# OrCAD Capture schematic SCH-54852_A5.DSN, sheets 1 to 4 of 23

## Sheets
1 C-07 CPU MISC: size C; title: MCIMX93-QSB; rev: A5; company: NXP Semiconductor; note: SCH-54852  PDF: SPF-54852; note: NO. 192 Liangjing Rd. Pudong New Area, ShangHai
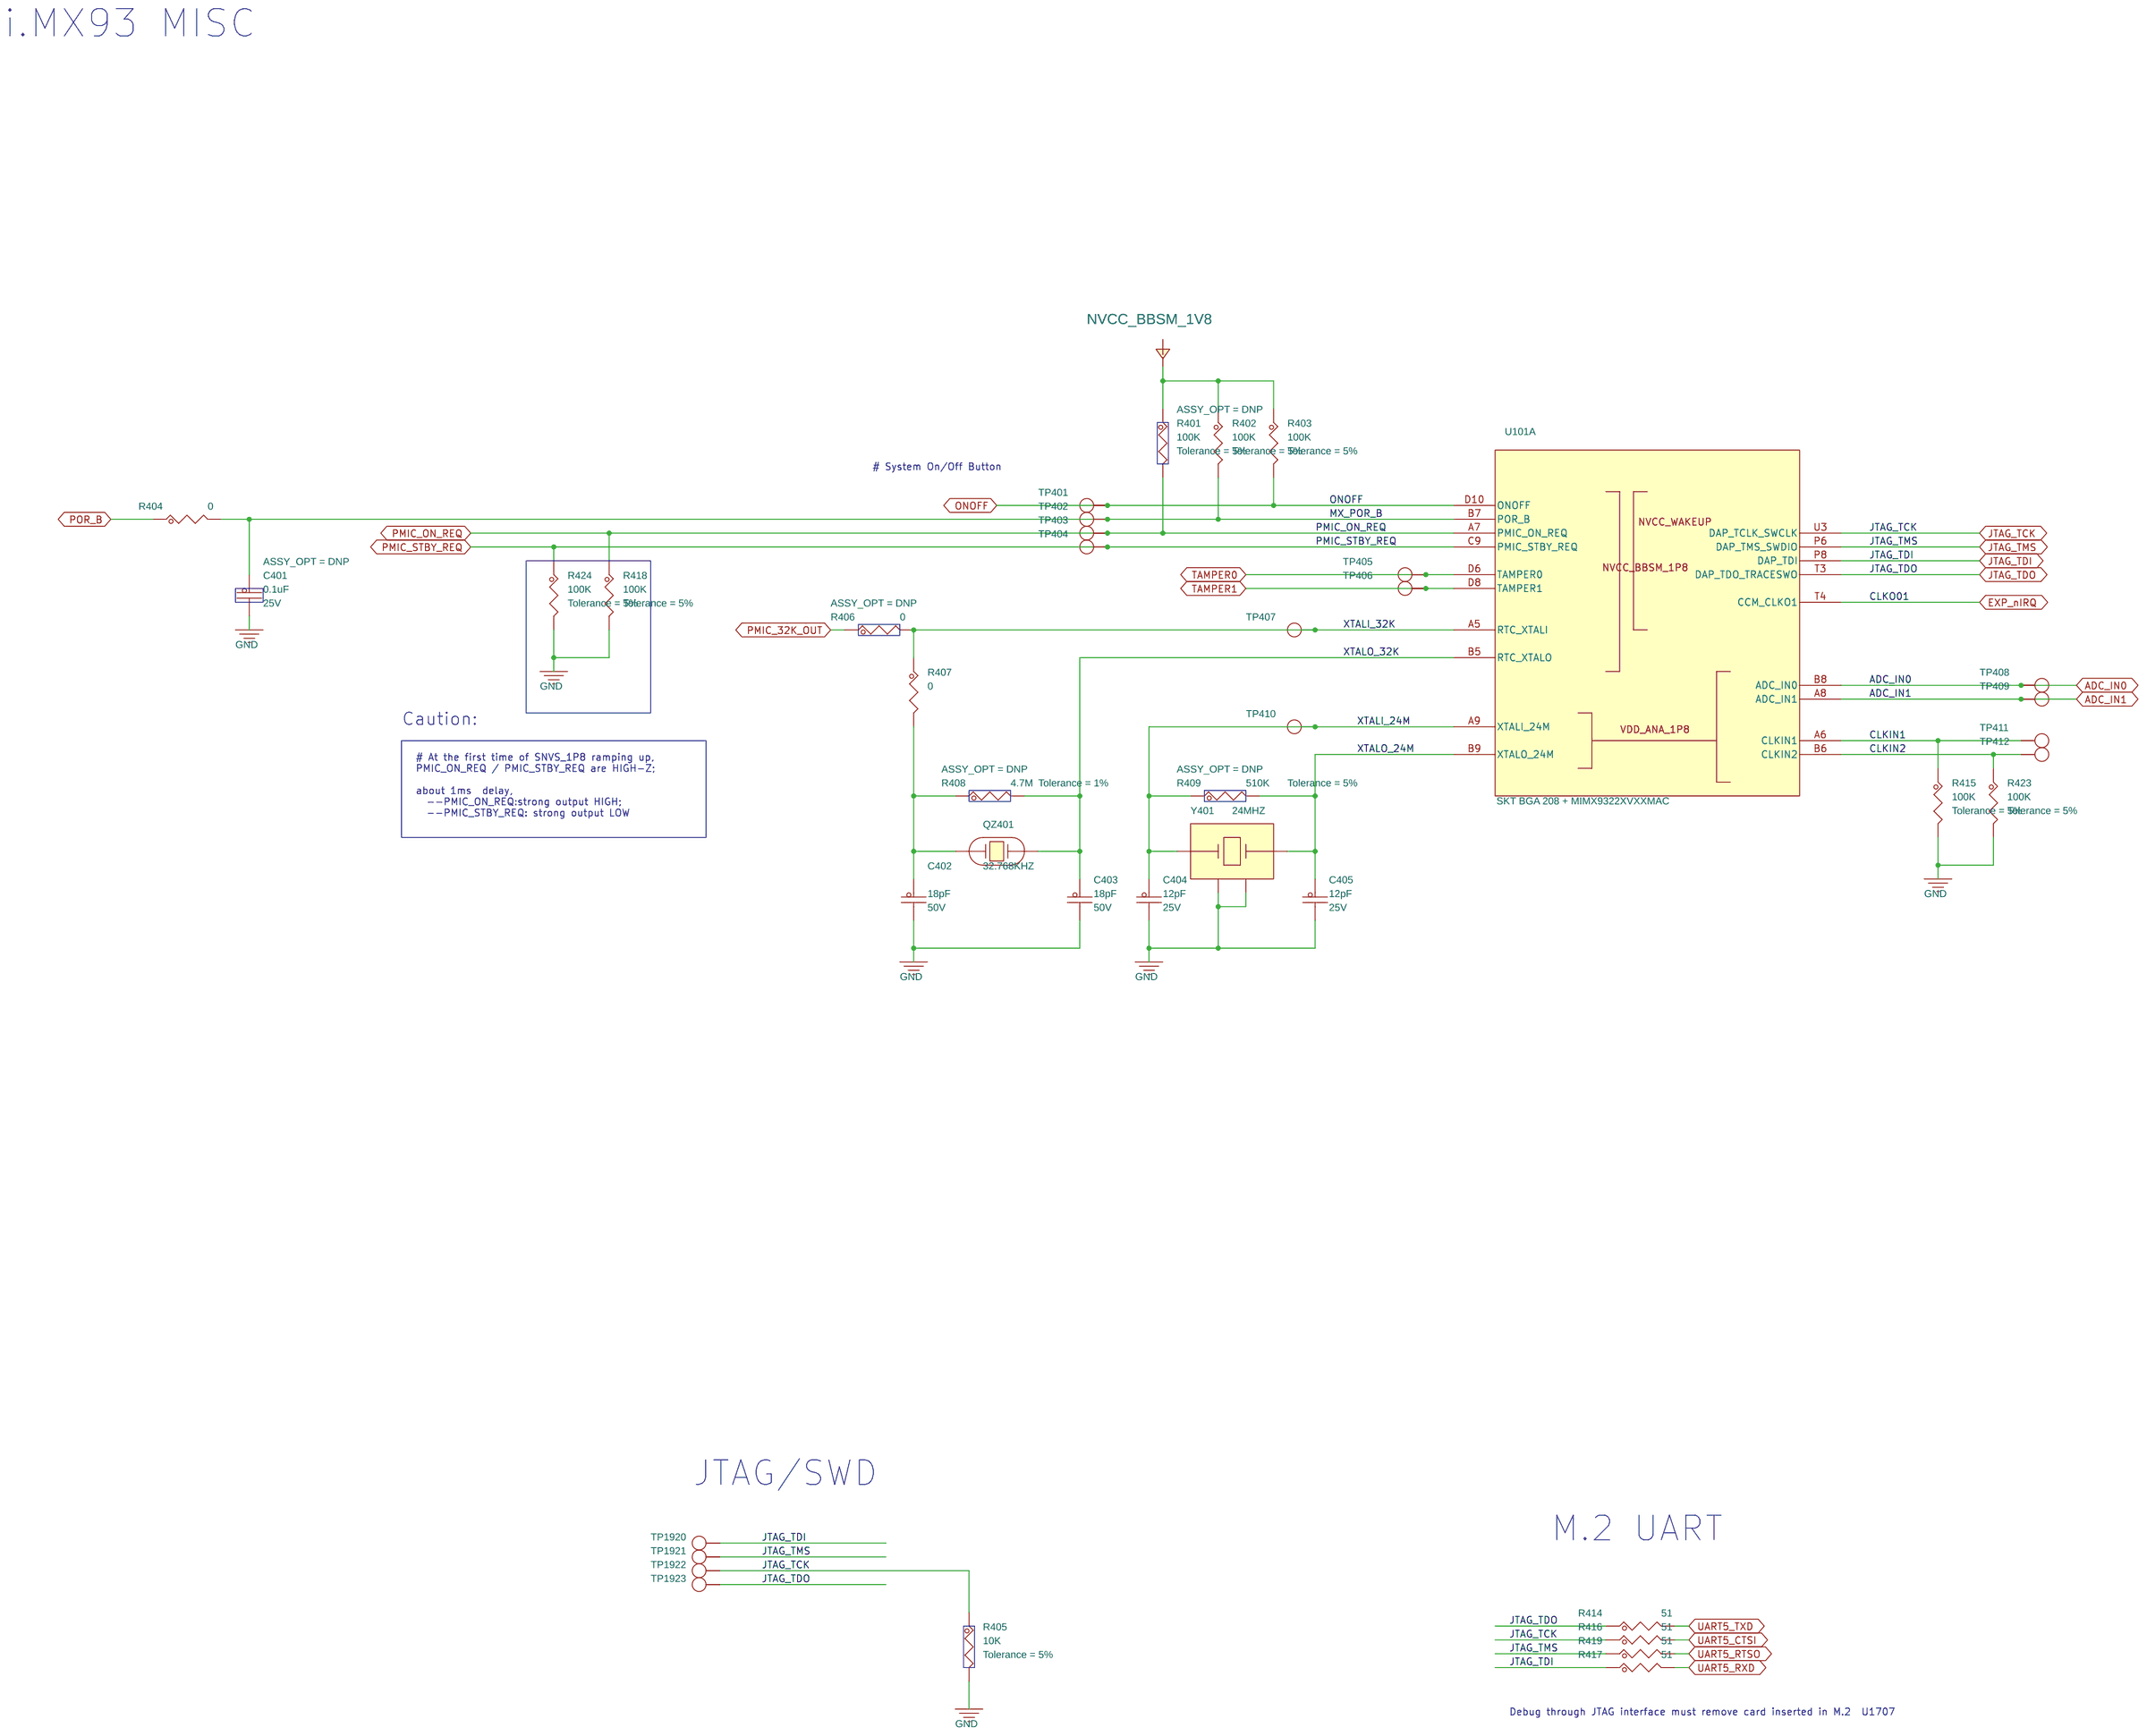
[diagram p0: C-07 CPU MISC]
2 X-23 IOMUX
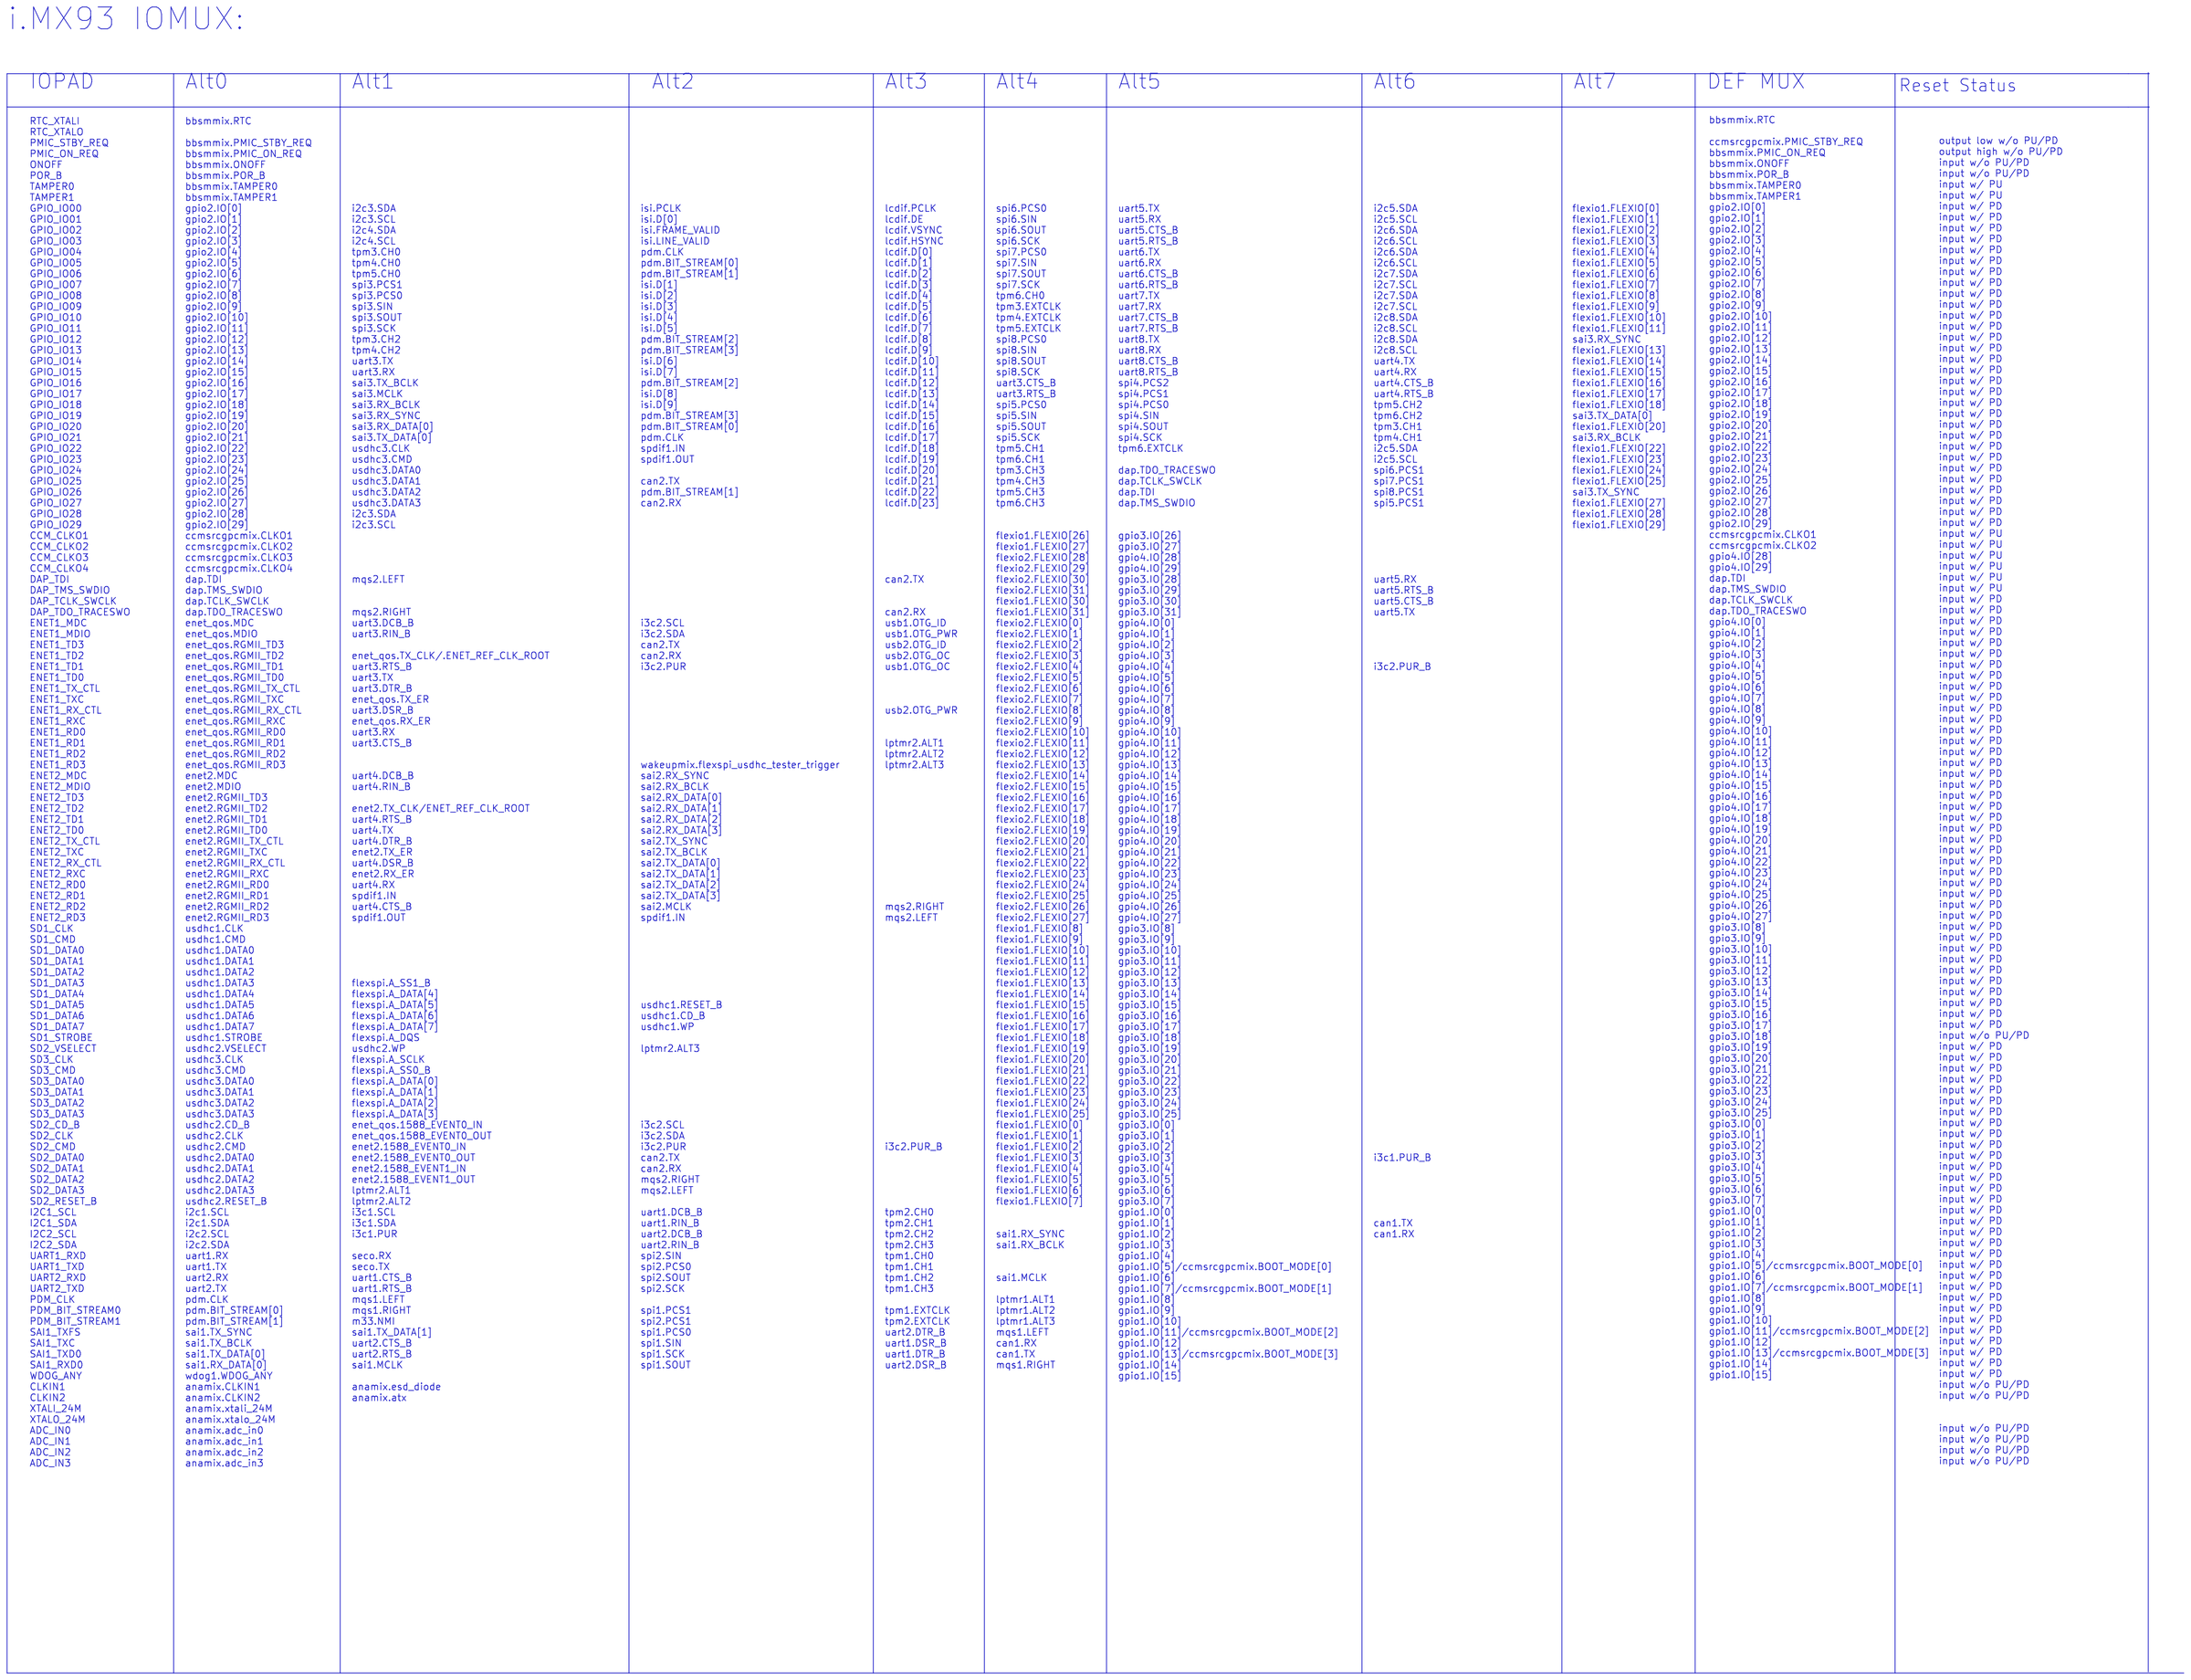
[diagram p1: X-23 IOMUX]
3 X-22 NOTE
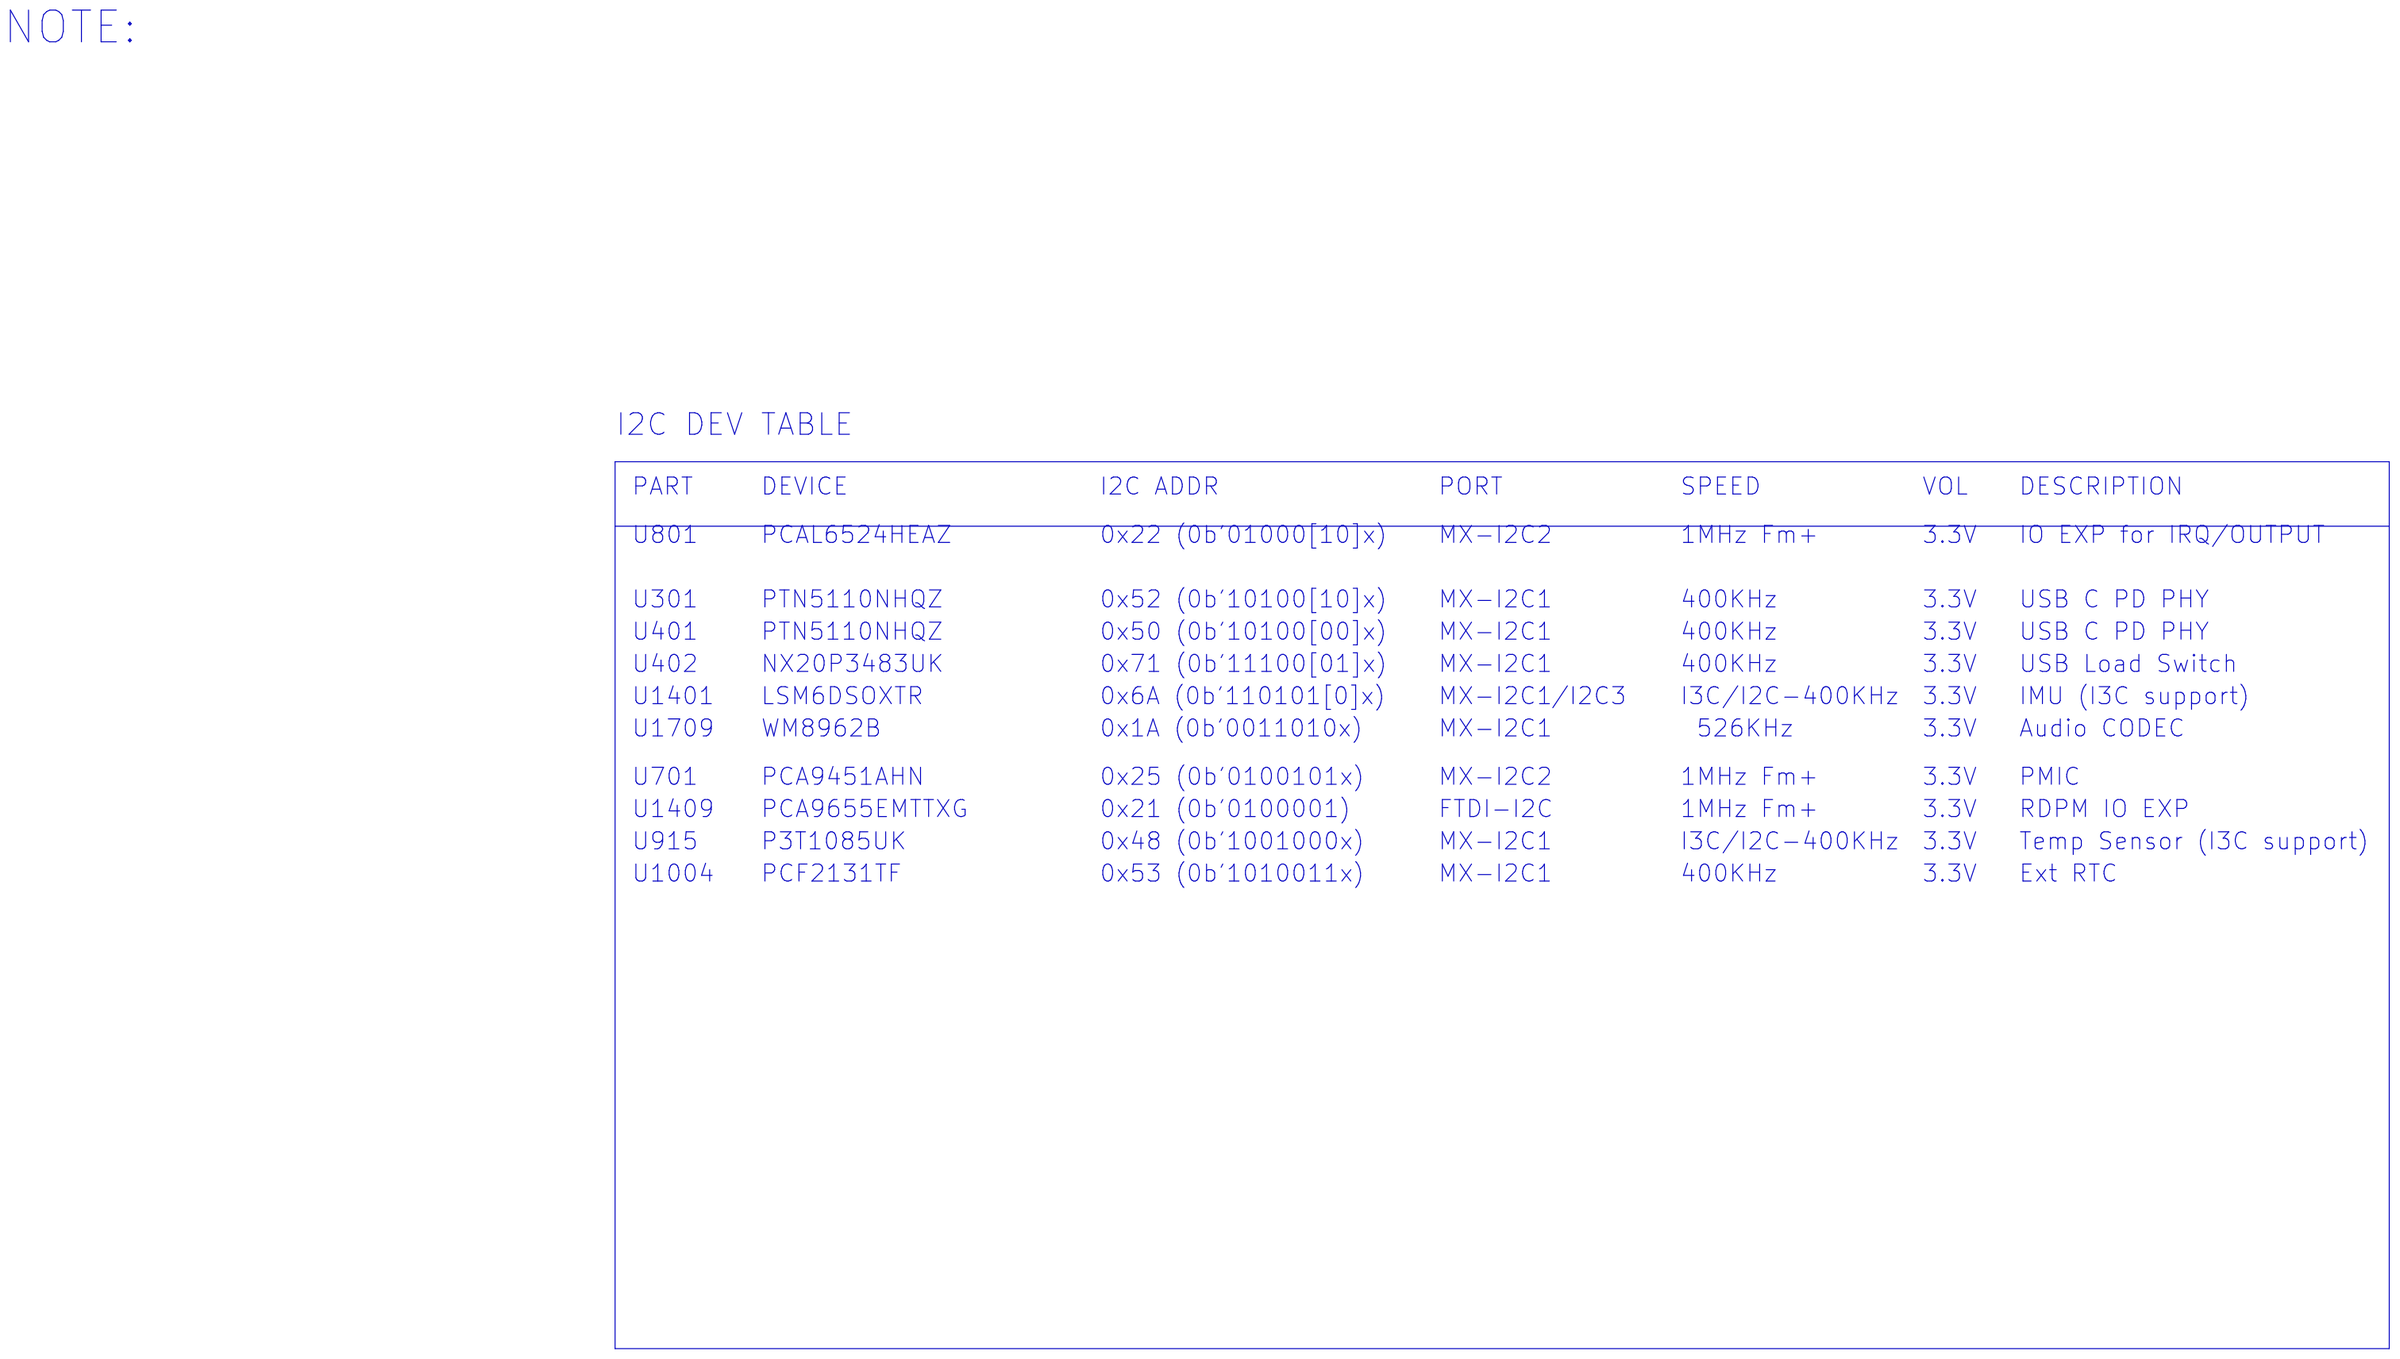
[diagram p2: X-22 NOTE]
4 X-21 Mechanics: size A
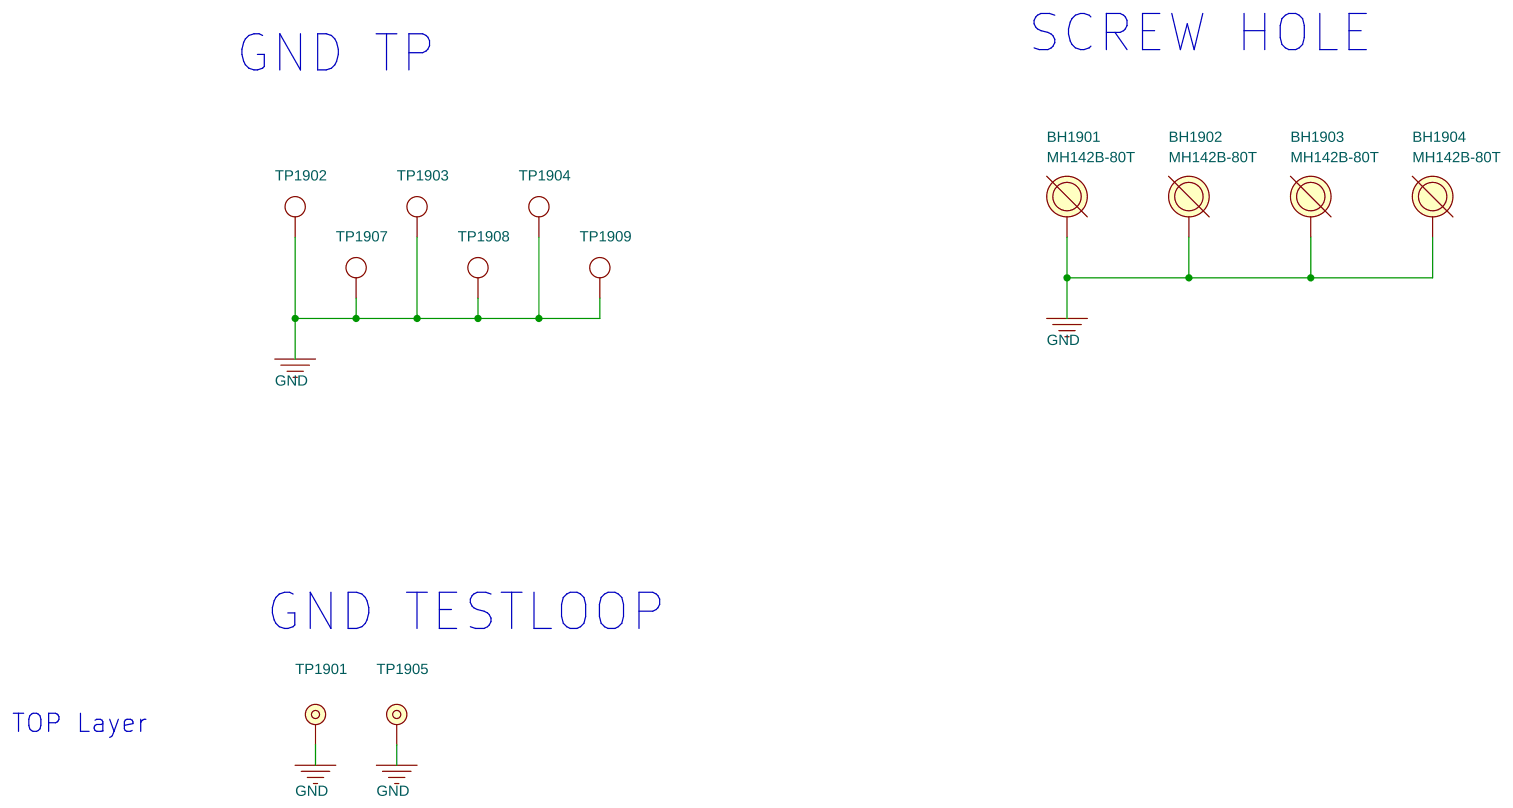
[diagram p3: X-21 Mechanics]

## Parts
sheet C-06 CPU IO/PHY
U101  SKT BGA 208 + MIMX9322XVXXMAC  [skt_bga208_0p5_17p725sq_elast]  (sections A,B,C,D,E,F)
sheet C-07 CPU MISC
C401  0.1uF  [0402_CC]
C402  18pF  [0201_CC]
C403  18pF  [0201_CC]
C404  12pF  [0201_CC]
C405  12pF  [0201_CC]
QZ401  32.768KHZ  [XTAL2-3P2X1P5-SM]
R401  100K  [0402_CC]
R402  100K  [0402_CC]
R403  100K  [0402_CC]
R404  0  [0201_CC]
R405  10K  [0402_CC]
R406  0  [0201_CC]
R407  0  [0201_CC]
R408  4.7M  [RC0402_25]
R409  510K  [0402_CC]
R414  51  [0402_CC]
R415  100K  [0402_CC]
R416  51  [0402_CC]
R417  51  [0402_CC]
R418  100K  [0402_CC]
R419  51  [0402_CC]
R423  100K  [0402_CC]
R424  100K  [0402_CC]
TP401  TPAD_020  [tpad_020]
TP402  TPAD_020  [tpad_020]
TP403  TPAD_020  [tpad_020]
TP404  TPAD_020  [tpad_020]
TP405  TPAD_020  [tpad_020]
TP406  TPAD_020  [tpad_020]
TP407  TPAD_015  [TPAD_015]
TP408  TPAD_020  [tpad_020]
TP409  TPAD_020  [tpad_020]
TP410  TPAD_015  [TPAD_015]
TP411  TPAD_020  [tpad_020]
TP412  TPAD_020  [tpad_020]
TP1920  TPAD_020  [tpad_020]
TP1921  TPAD_020  [tpad_020]
TP1922  TPAD_020  [tpad_020]
TP1923  TPAD_020  [tpad_020]
Y401  24MHZ  [xtlosc4_3p2x2p5mm_sm]
sheet X-21 Mechanics
BH1901  MH142B-80T  [mh142p080]
BH1902  MH142B-80T  [mh142p080]
BH1903  MH142B-80T  [mh142p080]
BH1904  MH142B-80T  [mh142p080]
TP1901  5123  [tp_th_063]
TP1902  TPAD_050  [TPAD_050]
TP1903  TPAD_050  [TPAD_050]
TP1904  TPAD_050  [TPAD_050]
TP1905  5123  [tp_th_063]
TP1907  TPAD_050  [TPAD_050]
TP1908  TPAD_050  [TPAD_050]
TP1909  TPAD_050  [TPAD_050]

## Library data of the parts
U101 = MIMX9322XVXxMAB_BGA208: SUBASSEMBLY SKT 208 BGA ELASTOMER SMT 0.5MM 414H AU + IC CPU CORTEX 2xA55 1.7GHz 3.2GT/s DDR -- FCPBGA208; AGILE_PN: TMP-CIP-20687; CAD_APPROVED: Yes; HEIGHT: 10.503mm; MFG_NAME01: SUBASSEMBLY; MFG_PN01: 211-81858,330-10033; PRE_APN: 750-10191; Package Type: SMD/SMT; ROHS: Yes
C401 = CAP_NP: CAP CER 0.1UF 25V 10% X5R 0402; AGILE_PN: 150-78633; ASSY_OPT: DNP; CAD_APPROVED: Yes; FPLIST: CC0402_25,CC0402_HD,0402_CC; HEIGHT: 0.55MM; MFG_NAME01: YAGEO AMERICA; MFG_PN01: CC0402KRX5R8BB104; Package Size: 0402; ROHS: Yes; Tolerance: 10%; VOLTAGE: 25V
C402 C403 = CAP_NP: CAP CER 18pF 50V 5% C0G 0201; AGILE_PN: 150-79476; CAD_APPROVED: Yes; FPLIST: CC0201,CC0201_HD,0201_CC; HEIGHT: 0.33MM; MFG_NAME01: MURATA; MFG_PN01: GRM0335C1H180JA01D; Package Size: 0201; Package Type: &#966;180mm Paper taping; ROHS: Yes; Tolerance: 5%; VOLTAGE: 50V
C404 C405 = CAP_NP: CAP CER 12PF 25V 5% C0G AEC-Q200 0201; AGILE_PN: 150-79813; CAD_APPROVED: Yes; FPLIST: CC0201,CC0201_HD,0201_CC; HEIGHT: 0.33MM; MFG_NAME01: TDK; MFG_PN01: CGA1A2C0G1E120J030BA; ROHS: Yes; Tolerance: 5%; VOLTAGE: 25V
QZ401 = XTAL: XTAL 32.768KHZ 12.5PF 20PPM 3.2X1.5MM SMT; AGILE_PN: 230-77653; CAD_APPROVED: Yes; HEIGHT: 0.9MM; MFG_NAME01: Abracon Corporation; MFG_PN01: ABS07-32.768KHZ-T; ROHS: Yes
R401 = RES: RES MF 100K 1/16W 5% 0402; AGILE_PN: 470-75597; ASSY_OPT: DNP; CAD_APPROVED: Yes; FPLIST: RC0402_25,RC0402_HD,0402_CC; HEIGHT: 0.40 MM; MFG_NAME01: VENKEL COMPANY; MFG_PN01: CR0402-16W-104JT; ROHS: Yes; Temp Range: -55C to +155C; Tolerance: 5%; VOLTAGE: 50V
R402 R403 R415 R418 R423 R424 = RES: RES MF 100K 1/16W 5% 0402; AGILE_PN: 470-75597; CAD_APPROVED: Yes; FPLIST: RC0402_25,RC0402_HD,0402_CC; HEIGHT: 0.40 MM; MFG_NAME01: VENKEL COMPANY; MFG_PN01: CR0402-16W-104JT; ROHS: Yes; Temp Range: -55C to +155C; Tolerance: 5%; VOLTAGE: 50V
R404 R407 = RES: RES MF ZERO OHM 1/20W -- 0201; AGILE_PN: 470-76631; CAD_APPROVED: Yes; FPLIST: RC0201,0201_CC,RC0201_X2; HEIGHT: 0.30 MM; MFG_NAME01: BOURNS; MFG_PN01: CR0201-J/-000GLF; ROHS: Yes
R405 = RES: RES MF 10K 1/16W 5% 0402; AGILE_PN: 470-75557; CAD_APPROVED: Yes; FPLIST: RC0402_25,RC0402_HD,0402_CC; HEIGHT: 0.4 MM; MFG_NAME01: VISHAY INTERTECHNOLOGY; MFG_PN01: CRCW040210K0JNED; ROHS: Yes; Tolerance: 5%
R406 = RES: RES MF ZERO OHM 1/20W -- 0201; AGILE_PN: 470-76631; ASSY_OPT: DNP; CAD_APPROVED: Yes; FPLIST: RC0201,0201_CC,RC0201_X2; HEIGHT: 0.30 MM; MFG_NAME01: BOURNS; MFG_PN01: CR0201-J/-000GLF; ROHS: Yes
R408 = RES: RES MF 4.7M  1/16W 1% 0402; AGILE_PN: 470-31250; ASSY_OPT: DNP; CAD_APPROVED: Yes; FPLIST: RC0402_25,RC0402_HD,0402_CC; HEIGHT: 0.40 MM; MFG_NAME01: YAGEO AMERICA; MFG_PN01: RC0402FR-074M7L; ROHS: Yes; Temp Range: -55°C ~ 155°C; Tolerance: 1%; VOLTAGE: 50V
R409 = RES: RES MF 510K 1/16W 5% 0402; AGILE_PN: 470-76166; ASSY_OPT: DNP; CAD_APPROVED: Yes; FPLIST: RC0402_25,RC0402_HD,0402_CC; HEIGHT: 0.4 MM; MFG_NAME01: PANASONIC; MFG_PN01: ERJ-2GEJ514X; ROHS: Yes; Tolerance: 5%
R414 R416 R417 R419 = RES: RES MF 51 OHM 1/16W 5% 0402; AGILE_PN: 470-76089; CAD_APPROVED: Yes; FPLIST: RC0402_25,RC0402_HD,0402_CC; HEIGHT: 0.40 MM; MFG_NAME01: YAGEO AMERICA; MFG_PN01: RC0402JR-0751RL; ROHS: Yes; Tolerance: 5%; VOLTAGE: 1/16W
TP401-TP406 TP408 TP409 TP411 TP412 TP1920-TP1923 = TESTLOOP: TEST POINT PAD 0.5MM DIA SMT, NO PART TO ORDER; AGILE_PN: 211-77484; ASSY_OPT: DNP; CAD_APPROVED: Yes; HEIGHT: 0.1MM; ROHS: Yes
TP407 TP410 = TESTLOOP: TEST POINT PAD 15MIL DIA SMT, NO PART TO ORDER; AGILE_PN: 211-76645; ASSY_OPT: DNP; CAD_APPROVED: Yes; HEIGHT: 0.1MM; MFG_NAME01: NOTACOMPONENT; MFG_PN01: NOTACOMPONENT; ROHS: Yes
Y401 = XTAL_13: XTAL 24MHZ 9pF -- SMT 3.2X2.5MM; AGILE_PN: 230-77392; CAD_APPROVED: Yes; HEIGHT: 0.60MM; MFG_NAME01: EPSON TOYOCOM CORPORATION; MFG_PN01: TSX-3225 24.0000MF15X-AC3; ROHS: Yes
BH1901-BH1904 = MOUNT_HOLE: MOUNTING HOLE DRILL 80MIL PAD 142MIL PLATED TH NO PART TO ORDER; AGILE_PN: 280-77354; CAD_APPROVED: Yes; HEIGHT: 0.1MM; ROHS: Yes
TP1901 TP1905 = T_POINT_TH: TEST POINT GREY 70X220 MIL TH; AGILE_PN: 210-80618; CAD_APPROVED: Yes; HEIGHT: 5.6MM; MFG_NAME01: KEYSTONE ELECTRONICS; Package Type: TH; ROHS: Yes
TP1902-TP1904 TP1907-TP1909 = TESTLOOP: TEST POINT PAD 50MIL DIA SMT, NO PART TO ORDER; AGILE_PN: 211-76644; ASSY_OPT: DNP; CAD_APPROVED: Yes; HEIGHT: 0.1MM; MFG_NAME01: NOTACOMPONENT; MFG_PN01: NOTACOMPONENT; ROHS: Yes

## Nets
GND: BH1901.1 BH1902.1 BH1903.1 BH1904.1 C401.2 C402.2 C403.2 C404.2 C405.2 R405.2 R415.2 R418.2 R423.2 R424.2 TP1901.1(TP) TP1902.1(Pin1) TP1903.1(Pin1) TP1904.1(Pin1) TP1905.1(TP) TP1907.1(Pin1) TP1908.1(Pin1) TP1909.1(Pin1) Y401.2 Y401.4 ; also on sheet 5 6 7 8 9 10 11 12 16 17 18 19 20 21 22 23
ADC_IN0: TP408.1(Pin1) U101.B8(ADC_IN0) ; also on sheet 21
ADC_IN1: TP409.1(Pin1) U101.A8(ADC_IN1) ; also on sheet 21
CLKIN1: R415.1 TP411.1(Pin1) U101.A6(CLKIN1)
CLKIN2: R423.1 TP412.1(Pin1) U101.B6(CLKIN2)
EXP_nIRQ: U101.T4(CCM_CLKO1) ; also on sheet 12
JTAG_TCK: R405.1 R416.1 TP1922.1(Pin1) U101.U3(DAP_TCLK_SWCLK) ; also on sheet 5
JTAG_TDI: R417.1 TP1920.1(Pin1) U101.P8(DAP_TDI) ; also on sheet 5
JTAG_TDO: R414.1 TP1923.1(Pin1) U101.T3(DAP_TDO_TRACESWO) ; also on sheet 5
JTAG_TMS: R419.1 TP1921.1(Pin1) U101.P6(DAP_TMS_SWDIO) ; also on sheet 5
MX_POR_B: C401.1 R402.2 R404.2 TP402.1(Pin1) U101.B7(POR_B)
NVCC_BBSM_1V8: R401.1 R402.1 R403.1 ; also on sheet 16 17 21
ONOFF: R403.2 TP401.1(Pin1) U101.D10(ONOFF) ; also on sheet 5 21
PMIC_32K_OUT: R406.1 ; also on sheet 7 17
PMIC_ON_REQ: R401.2 R418.1 TP403.1(Pin1) U101.A7(PMIC_ON_REQ) ; also on sheet 5 11 17
PMIC_STBY_REQ: R424.1 TP404.1(Pin1) U101.C9(PMIC_STBY_REQ) ; also on sheet 5 17
POR_B: R404.1 ; also on sheet 5 12 17
TAMPER0: TP405.1(Pin1) U101.D6(TAMPER0) ; also on sheet 21
TAMPER1: TP406.1(Pin1) U101.D8(TAMPER1) ; also on sheet 21
UART5_CTSI: R416.2 ; also on sheet 7
UART5_RTSO: R419.2 ; also on sheet 7
UART5_RXD: R417.2 ; also on sheet 7
UART5_TXD: R414.2 ; also on sheet 7
XTALI_24M: C404.1 R409.1 TP410.1(Pin1) U101.A9(XTALI_24M) Y401.1
XTALI_32K: R406.2 R407.1 TP407.1(Pin1) U101.A5(RTC_XTALI)
XTALO_24M: C405.1 R409.2 U101.B9(XTALO_24M) Y401.3
XTALO_32K: C403.1 QZ401.1 R408.2 U101.B5(RTC_XTALO)
N113524078: C402.1 QZ401.2 R407.2 R408.1

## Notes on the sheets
sheet 1
- i.MX93 MISC
- # System On/Off Button
- Caution:
- # At the first time of SNVS_1P8 ramping up,
  PMIC_ON_REQ / PMIC_STBY_REQ are HIGH-Z;
  about 1ms  delay,
    --PMIC_ON_REQ:strong output HIGH;
    --PMIC_STBY_REQ: strong output LOW
- JTAG/SWD
- M.2 UART
- Debug through JTAG interface must remove card inserted in M.2  U1707
sheet 2
- i.MX93 IOMUX:
- IOPAD
- Alt0
- Alt1
- Alt2
- Alt3
- Alt4
- Alt5
- Alt6
- Alt7
- DEF MUX
- Reset Status
- bbsmmix.RTC
  ccmsrcgpcmix.PMIC_STBY_REQ
  bbsmmix.PMIC_ON_REQ
  bbsmmix.ONOFF
  bbsmmix.POR_B
  bbsmmix.TAMPER0
  bbsmmix.TAMPER1
  gpio2.IO[0]
  gpio2.IO[1]
  gpio2.IO[2]
  gpio2.IO[3]
  gpio2.IO[4]
  gpio2.IO[5]
  gpio2.IO[6]
  gpio2.IO[7]
  gpio2.IO[8]
  gpio2.IO[9]
  gpio2.IO[10]
  gpio2.IO[11]
  gpio2.IO[12]
  gpio2.IO[13]
  gpio2.IO[14]
  gpio2.IO[15]
  gpio2.IO[16]
  gpio2.IO[17]
  gpio2.IO[18]
  gpio2.IO[19]
  gpio2.IO[20]
  gpio2.IO[21]
  gpio2.IO[22]
  gpio2.IO[23]
  gpio2.IO[24]
  gpio2.IO[25]
  gpio2.IO[26]
  gpio2.IO[27]
  gpio2.IO[28]
  gpio2.IO[29]
  ccmsrcgpcmix.CLKO1
  ccmsrcgpcmix.CLKO2
  gpio4.IO[28]
  gpio4.IO[29]
  dap.TDI
  dap.TMS_SWDIO
  dap.TCLK_SWCLK
  dap.TDO_TRACESWO
  gpio4.IO[0]
  gpio4.IO[1]
  gpio4.IO[2]
  gpio4.IO[3]
  gpio4.IO[4]
  gpio4.IO[5]
  gpio4.IO[6]
  gpio4.IO[7]
  gpio4.IO[8]
  gpio4.IO[9]
  gpio4.IO[10]
  gpio4.IO[11]
  gpio4.IO[12]
  gpio4.IO[13]
  gpio4.IO[14]
  gpio4.IO[15]
  gpio4.IO[16]
  gpio4.IO[17]
  gpio4.IO[18]
  gpio4.IO[19]
  gpio4.IO[20]
  gpio4.IO[21]
  gpio4.IO[22]
  gpio4.IO[23]
  gpio4.IO[24]
  gpio4.IO[25]
  gpio4.IO[26]
  gpio4.IO[27]
  gpio3.IO[8]
  gpio3.IO[9]
  gpio3.IO[10]
  gpio3.IO[11]
  gpio3.IO[12]
  gpio3.IO[13]
  gpio3.IO[14]
  gpio3.IO[15]
  gpio3.IO[16]
  gpio3.IO[17]
  gpio3.IO[18]
  gpio3.IO[19]
  gpio3.IO[20]
  gpio3.IO[21]
  gpio3.IO[22]
  gpio3.IO[23]
  gpio3.IO[24]
  gpio3.IO[25]
  gpio3.IO[0]
  gpio3.IO[1]
  gpio3.IO[2]
  gpio3.IO[3]
  gpio3.IO[4]
  gpio3.IO[5]
  gpio3.IO[6]
  gpio3.IO[7]
  gpio1.IO[0]
  gpio1.IO[1]
  gpio1.IO[2]
  gpio1.IO[3]
  gpio1.IO[4]
  gpio1.IO[5]/ccmsrcgpcmix.BOOT_MODE[0]
  gpio1.IO[6]
  gpio1.IO[7]/ccmsrcgpcmix.BOOT_MODE[1]
  gpio1.IO[8]
  gpio1.IO[9]
  gpio1.IO[10]
  gpio1.IO[11]/ccmsrcgpcmix.BOOT_MODE[2]
  gpio1.IO[12]
  gpio1.IO[13]/ccmsrcgpcmix.BOOT_MODE[3]
  gpio1.IO[14]
  gpio1.IO[15]
- output low w/o PU/PD
  output high w/o PU/PD
  input w/o PU/PD
  input w/o PU/PD
  input w/ PU
  input w/ PU
  input w/ PD
  input w/ PD
  input w/ PD
  input w/ PD
  input w/ PD
  input w/ PD
  input w/ PD
  input w/ PD
  input w/ PD
  input w/ PD
  input w/ PD
  input w/ PD
  input w/ PD
  input w/ PD
  input w/ PD
  input w/ PD
  input w/ PD
  input w/ PD
  input w/ PD
  input w/ PD
  input w/ PD
  input w/ PD
  input w/ PD
  input w/ PD
  input w/ PD
  input w/ PD
  input w/ PD
  input w/ PD
  input w/ PD
  input w/ PD
  input w/ PU
  input w/ PU
  input w/ PU
  input w/ PU
  input w/ PU
  input w/ PU
  input w/ PD
  input w/ PD
  input w/ PD
  input w/ PD
  input w/ PD
  input w/ PD
  input w/ PD
  input w/ PD
  input w/ PD
  input w/ PD
  input w/ PD
  input w/ PD
  input w/ PD
  input w/ PD
  input w/ PD
  input w/ PD
  input w/ PD
  input w/ PD
  input w/ PD
  input w/ PD
  input w/ PD
  input w/ PD
  input w/ PD
  input w/ PD
  input w/ PD
  input w/ PD
  input w/ PD
  input w/ PD
  input w/ PD
  input w/ PD
  input w/ PD
  input w/ PD
  input w/ PD
  input w/ PD
  input w/ PD
  input w/ PD
  input w/ PD
  input w/ PD
  input w/ PD
  input w/ PD
  input w/o PU/PD
  input w/ PD
  input w/ PD
  input w/ PD
  input w/ PD
  input w/ PD
  input w/ PD
  input w/ PD
  input w/ PD
  input w/ PD
  input w/ PD
  input w/ PD
  input w/ PD
  input w/ PD
  input w/ PD
  input w/ PD
  input w/ PD
  input w/ PD
  input w/ PD
  input w/ PD
  input w/ PD
  input w/ PD
  input w/ PD
  input w/ PD
  input w/ PD
  input w/ PD
  input w/ PD
  input w/ PD
  input w/ PD
  input w/ PD
  input w/ PD
  input w/ PD
  input w/o PU/PD
  input w/o PU/PD
  input w/o PU/PD
  input w/o PU/PD
  input w/o PU/PD
  input w/o PU/PD
- RTC_XTALI
  RTC_XTALO
  PMIC_STBY_REQ
  PMIC_ON_REQ
  ONOFF
  POR_B
  TAMPER0
  TAMPER1
  GPIO_IO00
  GPIO_IO01
  GPIO_IO02
  GPIO_IO03
  GPIO_IO04
  GPIO_IO05
  GPIO_IO06
  GPIO_IO07
  GPIO_IO08
  GPIO_IO09
  GPIO_IO10
  GPIO_IO11
  GPIO_IO12
  GPIO_IO13
  GPIO_IO14
  GPIO_IO15
  GPIO_IO16
  GPIO_IO17
  GPIO_IO18
  GPIO_IO19
  GPIO_IO20
  GPIO_IO21
  GPIO_IO22
  GPIO_IO23
  GPIO_IO24
  GPIO_IO25
  GPIO_IO26
  GPIO_IO27
  GPIO_IO28
  GPIO_IO29
  CCM_CLKO1
  CCM_CLKO2
  CCM_CLKO3
  CCM_CLKO4
  DAP_TDI
  DAP_TMS_SWDIO
  DAP_TCLK_SWCLK
  DAP_TDO_TRACESWO
  ENET1_MDC
  ENET1_MDIO
  ENET1_TD3
  ENET1_TD2
  ENET1_TD1
  ENET1_TD0
  ENET1_TX_CTL
  ENET1_TXC
  ENET1_RX_CTL
  ENET1_RXC
  ENET1_RD0
  ENET1_RD1
  ENET1_RD2
  ENET1_RD3
  ENET2_MDC
  ENET2_MDIO
  ENET2_TD3
  ENET2_TD2
  ENET2_TD1
  ENET2_TD0
  ENET2_TX_CTL
  ENET2_TXC
  ENET2_RX_CTL
  ENET2_RXC
  ENET2_RD0
  ENET2_RD1
  ENET2_RD2
  ENET2_RD3
  SD1_CLK
  SD1_CMD
  SD1_DATA0
  SD1_DATA1
  SD1_DATA2
  SD1_DATA3
  SD1_DATA4
  SD1_DATA5
  SD1_DATA6
  SD1_DATA7
  SD1_STROBE
  SD2_VSELECT
  SD3_CLK
  SD3_CMD
  SD3_DATA0
  SD3_DATA1
  SD3_DATA2
  SD3_DATA3
  SD2_CD_B
  SD2_CLK
  SD2_CMD
  SD2_DATA0
  SD2_DATA1
  SD2_DATA2
  SD2_DATA3
  SD2_RESET_B
  I2C1_SCL
  I2C1_SDA
  I2C2_SCL
  I2C2_SDA
  UART1_RXD
  UART1_TXD
  UART2_RXD
  UART2_TXD
  PDM_CLK
  PDM_BIT_STREAM0
  PDM_BIT_STREAM1
  SAI1_TXFS
  SAI1_TXC
  SAI1_TXD0
  SAI1_RXD0
  WDOG_ANY
  CLKIN1
  CLKIN2
  XTALI_24M
  XTALO_24M
  ADC_IN0
  ADC_IN1
  ADC_IN2
  ADC_IN3
- bbsmmix.RTC
  bbsmmix.PMIC_STBY_REQ
  bbsmmix.PMIC_ON_REQ
  bbsmmix.ONOFF
  bbsmmix.POR_B
  bbsmmix.TAMPER0
  bbsmmix.TAMPER1
  gpio2.IO[0]
  gpio2.IO[1]
  gpio2.IO[2]
  gpio2.IO[3]
  gpio2.IO[4]
  gpio2.IO[5]
  gpio2.IO[6]
  gpio2.IO[7]
  gpio2.IO[8]
  gpio2.IO[9]
  gpio2.IO[10]
  gpio2.IO[11]
  gpio2.IO[12]
  gpio2.IO[13]
  gpio2.IO[14]
  gpio2.IO[15]
  gpio2.IO[16]
  gpio2.IO[17]
  gpio2.IO[18]
  gpio2.IO[19]
  gpio2.IO[20]
  gpio2.IO[21]
  gpio2.IO[22]
  gpio2.IO[23]
  gpio2.IO[24]
  gpio2.IO[25]
  gpio2.IO[26]
  gpio2.IO[27]
  gpio2.IO[28]
  gpio2.IO[29]
  ccmsrcgpcmix.CLKO1
  ccmsrcgpcmix.CLKO2
  ccmsrcgpcmix.CLKO3
  ccmsrcgpcmix.CLKO4
  dap.TDI
  dap.TMS_SWDIO
  dap.TCLK_SWCLK
  dap.TDO_TRACESWO
  enet_qos.MDC
  enet_qos.MDIO
  enet_qos.RGMII_TD3
  enet_qos.RGMII_TD2
  enet_qos.RGMII_TD1
  enet_qos.RGMII_TD0
  enet_qos.RGMII_TX_CTL
  enet_qos.RGMII_TXC
  enet_qos.RGMII_RX_CTL
  enet_qos.RGMII_RXC
  enet_qos.RGMII_RD0
  enet_qos.RGMII_RD1
  enet_qos.RGMII_RD2
  enet_qos.RGMII_RD3
  enet2.MDC
  enet2.MDIO
  enet2.RGMII_TD3
  enet2.RGMII_TD2
  enet2.RGMII_TD1
  enet2.RGMII_TD0
  enet2.RGMII_TX_CTL
  enet2.RGMII_TXC
  enet2.RGMII_RX_CTL
  enet2.RGMII_RXC
  enet2.RGMII_RD0
  enet2.RGMII_RD1
  enet2.RGMII_RD2
  enet2.RGMII_RD3
  usdhc1.CLK
  usdhc1.CMD
  usdhc1.DATA0
  usdhc1.DATA1
  usdhc1.DATA2
  usdhc1.DATA3
  usdhc1.DATA4
  usdhc1.DATA5
  usdhc1.DATA6
  usdhc1.DATA7
  usdhc1.STROBE
  usdhc2.VSELECT
  usdhc3.CLK
  usdhc3.CMD
  usdhc3.DATA0
  usdhc3.DATA1
  usdhc3.DATA2
  usdhc3.DATA3
  usdhc2.CD_B
  usdhc2.CLK
  usdhc2.CMD
  usdhc2.DATA0
  usdhc2.DATA1
  usdhc2.DATA2
  usdhc2.DATA3
  usdhc2.RESET_B
  i2c1.SCL
  i2c1.SDA
  i2c2.SCL
  i2c2.SDA
  uart1.RX
  uart1.TX
  uart2.RX
  uart2.TX
  pdm.CLK
  pdm.BIT_STREAM[0]
  pdm.BIT_STREAM[1]
  sai1.TX_SYNC
  sai1.TX_BCLK
  sai1.TX_DATA[0]
  sai1.RX_DATA[0]
  wdog1.WDOG_ANY
  anamix.CLKIN1
  anamix.CLKIN2
  anamix.xtali_24M
  anamix.xtalo_24M
  anamix.adc_in0
  anamix.adc_in1
  anamix.adc_in2
  anamix.adc_in3
- i2c3.SDA
  i2c3.SCL
  i2c4.SDA
  i2c4.SCL
  tpm3.CH0
  tpm4.CH0
  tpm5.CH0
  spi3.PCS1
  spi3.PCS0
  spi3.SIN
  spi3.SOUT
  spi3.SCK
  tpm3.CH2
  tpm4.CH2
  uart3.TX
  uart3.RX
  sai3.TX_BCLK
  sai3.MCLK
  sai3.RX_BCLK
  sai3.RX_SYNC
  sai3.RX_DATA[0]
  sai3.TX_DATA[0]
  usdhc3.CLK
  usdhc3.CMD
  usdhc3.DATA0
  usdhc3.DATA1
  usdhc3.DATA2
  usdhc3.DATA3
  i2c3.SDA
  i2c3.SCL
  mqs2.LEFT
  mqs2.RIGHT
  uart3.DCB_B
  uart3.RIN_B
  enet_qos.TX_CLK/.ENET_REF_CLK_ROOT
  uart3.RTS_B
  uart3.TX
  uart3.DTR_B
  enet_qos.TX_ER
  uart3.DSR_B
  enet_qos.RX_ER
  uart3.RX
  uart3.CTS_B
  uart4.DCB_B
  uart4.RIN_B
  enet2.TX_CLK/ENET_REF_CLK_ROOT
  uart4.RTS_B
  uart4.TX
  uart4.DTR_B
  enet2.TX_ER
  uart4.DSR_B
  enet2.RX_ER
  uart4.RX
  spdif1.IN
  uart4.CTS_B
  spdif1.OUT
  flexspi.A_SS1_B
  flexspi.A_DATA[4]
  flexspi.A_DATA[5]
  flexspi.A_DATA[6]
  flexspi.A_DATA[7]
  flexspi.A_DQS
  usdhc2.WP
  flexspi.A_SCLK
  flexspi.A_SS0_B
  flexspi.A_DATA[0]
  flexspi.A_DATA[1]
  flexspi.A_DATA[2]
  flexspi.A_DATA[3]
  enet_qos.1588_EVENT0_IN
  enet_qos.1588_EVENT0_OUT
  enet2.1588_EVENT0_IN
  enet2.1588_EVENT0_OUT
  enet2.1588_EVENT1_IN
  enet2.1588_EVENT1_OUT
  lptmr2.ALT1
  lptmr2.ALT2
  i3c1.SCL
  i3c1.SDA
  i3c1.PUR
  seco.RX
  seco.TX
  uart1.CTS_B
  uart1.RTS_B
  mqs1.LEFT
  mqs1.RIGHT
  m33.NMI
  sai1.TX_DATA[1]
  uart2.CTS_B
  uart2.RTS_B
  sai1.MCLK
  anamix.esd_diode
  anamix.atx
- isi.PCLK
  isi.D[0]
  isi.FRAME_VALID
  isi.LINE_VALID
  pdm.CLK
  pdm.BIT_STREAM[0]
  pdm.BIT_STREAM[1]
  isi.D[1]
  isi.D[2]
  isi.D[3]
  isi.D[4]
  isi.D[5]
  pdm.BIT_STREAM[2]
  pdm.BIT_STREAM[3]
  isi.D[6]
  isi.D[7]
  pdm.BIT_STREAM[2]
  isi.D[8]
  isi.D[9]
  pdm.BIT_STREAM[3]
  pdm.BIT_STREAM[0]
  pdm.CLK
  spdif1.IN
  spdif1.OUT
  can2.TX
  pdm.BIT_STREAM[1]
  can2.RX
  i3c2.SCL
  i3c2.SDA
  can2.TX
  can2.RX
  i3c2.PUR
  wakeupmix.flexspi_usdhc_tester_trigger
  sai2.RX_SYNC
  sai2.RX_BCLK
  sai2.RX_DATA[0]
  sai2.RX_DATA[1]
  sai2.RX_DATA[2]
  sai2.RX_DATA[3]
  sai2.TX_SYNC
  sai2.TX_BCLK
  sai2.TX_DATA[0]
  sai2.TX_DATA[1]
  sai2.TX_DATA[2]
  sai2.TX_DATA[3]
  sai2.MCLK
  spdif1.IN
  usdhc1.RESET_B
  usdhc1.CD_B
  usdhc1.WP
  lptmr2.ALT3
  i3c2.SCL
  i3c2.SDA
  i3c2.PUR
  can2.TX
  can2.RX
  mqs2.RIGHT
  mqs2.LEFT
  uart1.DCB_B
  uart1.RIN_B
  uart2.DCB_B
  uart2.RIN_B
  spi2.SIN
  spi2.PCS0
  spi2.SOUT
  spi2.SCK
  spi1.PCS1
  spi2.PCS1
  spi1.PCS0
  spi1.SIN
  spi1.SCK
  spi1.SOUT
- lcdif.PCLK
  lcdif.DE
  lcdif.VSYNC
  lcdif.HSYNC
  lcdif.D[0]
  lcdif.D[1]
  lcdif.D[2]
  lcdif.D[3]
  lcdif.D[4]
  lcdif.D[5]
  lcdif.D[6]
  lcdif.D[7]
  lcdif.D[8]
  lcdif.D[9]
  lcdif.D[10]
  lcdif.D[11]
  lcdif.D[12]
  lcdif.D[13]
  lcdif.D[14]
  lcdif.D[15]
  lcdif.D[16]
  lcdif.D[17]
  lcdif.D[18]
  lcdif.D[19]
  lcdif.D[20]
  lcdif.D[21]
  lcdif.D[22]
  lcdif.D[23]
  can2.TX
  can2.RX
  usb1.OTG_ID
  usb1.OTG_PWR
  usb2.OTG_ID
  usb2.OTG_OC
  usb1.OTG_OC
  usb2.OTG_PWR
  lptmr2.ALT1
  lptmr2.ALT2
  lptmr2.ALT3
  mqs2.RIGHT
  mqs2.LEFT
  i3c2.PUR_B
  tpm2.CH0
  tpm2.CH1
  tpm2.CH2
  tpm2.CH3
  tpm1.CH0
  tpm1.CH1
  tpm1.CH2
  tpm1.CH3
  tpm1.EXTCLK
  tpm2.EXTCLK
  uart2.DTR_B
  uart1.DSR_B
  uart1.DTR_B
  uart2.DSR_B
- spi6.PCS0
  spi6.SIN
  spi6.SOUT
  spi6.SCK
  spi7.PCS0
  spi7.SIN
  spi7.SOUT
  spi7.SCK
  tpm6.CH0
  tpm3.EXTCLK
  tpm4.EXTCLK
  tpm5.EXTCLK
  spi8.PCS0
  spi8.SIN
  spi8.SOUT
  spi8.SCK
  uart3.CTS_B
  uart3.RTS_B
  spi5.PCS0
  spi5.SIN
  spi5.SOUT
  spi5.SCK
  tpm5.CH1
  tpm6.CH1
  tpm3.CH3
  tpm4.CH3
  tpm5.CH3
  tpm6.CH3
  flexio1.FLEXIO[26]
  flexio1.FLEXIO[27]
  flexio2.FLEXIO[28]
  flexio2.FLEXIO[29]
  flexio2.FLEXIO[30]
  flexio2.FLEXIO[31]
  flexio1.FLEXIO[30]
  flexio1.FLEXIO[31]
  flexio2.FLEXIO[0]
  flexio2.FLEXIO[1]
  flexio2.FLEXIO[2]
  flexio2.FLEXIO[3]
  flexio2.FLEXIO[4]
  flexio2.FLEXIO[5]
  flexio2.FLEXIO[6]
  flexio2.FLEXIO[7]
  flexio2.FLEXIO[8]
  flexio2.FLEXIO[9]
  flexio2.FLEXIO[10]
  flexio2.FLEXIO[11]
  flexio2.FLEXIO[12]
  flexio2.FLEXIO[13]
  flexio2.FLEXIO[14]
  flexio2.FLEXIO[15]
  flexio2.FLEXIO[16]
  flexio2.FLEXIO[17]
  flexio2.FLEXIO[18]
  flexio2.FLEXIO[19]
  flexio2.FLEXIO[20]
  flexio2.FLEXIO[21]
  flexio2.FLEXIO[22]
  flexio2.FLEXIO[23]
  flexio2.FLEXIO[24]
  flexio2.FLEXIO[25]
  flexio2.FLEXIO[26]
  flexio2.FLEXIO[27]
  flexio1.FLEXIO[8]
  flexio1.FLEXIO[9]
  flexio1.FLEXIO[10]
  flexio1.FLEXIO[11]
  flexio1.FLEXIO[12]
  flexio1.FLEXIO[13]
  flexio1.FLEXIO[14]
  flexio1.FLEXIO[15]
  flexio1.FLEXIO[16]
  flexio1.FLEXIO[17]
  flexio1.FLEXIO[18]
  flexio1.FLEXIO[19]
  flexio1.FLEXIO[20]
  flexio1.FLEXIO[21]
  flexio1.FLEXIO[22]
  flexio1.FLEXIO[23]
  flexio1.FLEXIO[24]
  flexio1.FLEXIO[25]
  flexio1.FLEXIO[0]
  flexio1.FLEXIO[1]
  flexio1.FLEXIO[2]
  flexio1.FLEXIO[3]
  flexio1.FLEXIO[4]
  flexio1.FLEXIO[5]
  flexio1.FLEXIO[6]
  flexio1.FLEXIO[7]
  sai1.RX_SYNC
  sai1.RX_BCLK
  sai1.MCLK
  lptmr1.ALT1
  lptmr1.ALT2
  lptmr1.ALT3
  mqs1.LEFT
  can1.RX
  can1.TX
  mqs1.RIGHT
- uart5.TX
  uart5.RX
  uart5.CTS_B
  uart5.RTS_B
  uart6.TX
  uart6.RX
  uart6.CTS_B
  uart6.RTS_B
  uart7.TX
  uart7.RX
  uart7.CTS_B
  uart7.RTS_B
  uart8.TX
  uart8.RX
  uart8.CTS_B
  uart8.RTS_B
  spi4.PCS2
  spi4.PCS1
  spi4.PCS0
  spi4.SIN
  spi4.SOUT
  spi4.SCK
  tpm6.EXTCLK
  dap.TDO_TRACESWO
  dap.TCLK_SWCLK
  dap.TDI
  dap.TMS_SWDIO
  gpio3.IO[26]
  gpio3.IO[27]
  gpio4.IO[28]
  gpio4.IO[29]
  gpio3.IO[28]
  gpio3.IO[29]
  gpio3.IO[30]
  gpio3.IO[31]
  gpio4.IO[0]
  gpio4.IO[1]
  gpio4.IO[2]
  gpio4.IO[3]
  gpio4.IO[4]
  gpio4.IO[5]
  gpio4.IO[6]
  gpio4.IO[7]
  gpio4.IO[8]
  gpio4.IO[9]
  gpio4.IO[10]
  gpio4.IO[11]
  gpio4.IO[12]
  gpio4.IO[13]
  gpio4.IO[14]
  gpio4.IO[15]
  gpio4.IO[16]
  gpio4.IO[17]
  gpio4.IO[18]
  gpio4.IO[19]
  gpio4.IO[20]
  gpio4.IO[21]
  gpio4.IO[22]
  gpio4.IO[23]
  gpio4.IO[24]
  gpio4.IO[25]
  gpio4.IO[26]
  gpio4.IO[27]
  gpio3.IO[8]
  gpio3.IO[9]
  gpio3.IO[10]
  gpio3.IO[11]
  gpio3.IO[12]
  gpio3.IO[13]
  gpio3.IO[14]
  gpio3.IO[15]
  gpio3.IO[16]
  gpio3.IO[17]
  gpio3.IO[18]
  gpio3.IO[19]
  gpio3.IO[20]
  gpio3.IO[21]
  gpio3.IO[22]
  gpio3.IO[23]
  gpio3.IO[24]
  gpio3.IO[25]
  gpio3.IO[0]
  gpio3.IO[1]
  gpio3.IO[2]
  gpio3.IO[3]
  gpio3.IO[4]
  gpio3.IO[5]
  gpio3.IO[6]
  gpio3.IO[7]
  gpio1.IO[0]
  gpio1.IO[1]
  gpio1.IO[2]
  gpio1.IO[3]
  gpio1.IO[4]
  gpio1.IO[5]/ccmsrcgpcmix.BOOT_MODE[0]
  gpio1.IO[6]
  gpio1.IO[7]/ccmsrcgpcmix.BOOT_MODE[1]
  gpio1.IO[8]
  gpio1.IO[9]
  gpio1.IO[10]
  gpio1.IO[11]/ccmsrcgpcmix.BOOT_MODE[2]
  gpio1.IO[12]
  gpio1.IO[13]/ccmsrcgpcmix.BOOT_MODE[3]
  gpio1.IO[14]
  gpio1.IO[15]
- i2c5.SDA
  i2c5.SCL
  i2c6.SDA
  i2c6.SCL
  i2c6.SDA
  i2c6.SCL
  i2c7.SDA
  i2c7.SCL
  i2c7.SDA
  i2c7.SCL
  i2c8.SDA
  i2c8.SCL
  i2c8.SDA
  i2c8.SCL
  uart4.TX
  uart4.RX
  uart4.CTS_B
  uart4.RTS_B
  tpm5.CH2
  tpm6.CH2
  tpm3.CH1
  tpm4.CH1
  i2c5.SDA
  i2c5.SCL
  spi6.PCS1
  spi7.PCS1
  spi8.PCS1
  spi5.PCS1
  uart5.RX
  uart5.RTS_B
  uart5.CTS_B
  uart5.TX
  i3c2.PUR_B
  i3c1.PUR_B
  can1.TX
  can1.RX
- flexio1.FLEXIO[0]
  flexio1.FLEXIO[1]
  flexio1.FLEXIO[2]
  flexio1.FLEXIO[3]
  flexio1.FLEXIO[4]
  flexio1.FLEXIO[5]
  flexio1.FLEXIO[6]
  flexio1.FLEXIO[7]
  flexio1.FLEXIO[8]
  flexio1.FLEXIO[9]
  flexio1.FLEXIO[10]
  flexio1.FLEXIO[11]
  sai3.RX_SYNC
  flexio1.FLEXIO[13]
  flexio1.FLEXIO[14]
  flexio1.FLEXIO[15]
  flexio1.FLEXIO[16]
  flexio1.FLEXIO[17]
  flexio1.FLEXIO[18]
  sai3.TX_DATA[0]
  flexio1.FLEXIO[20]
  sai3.RX_BCLK
  flexio1.FLEXIO[22]
  flexio1.FLEXIO[23]
  flexio1.FLEXIO[24]
  flexio1.FLEXIO[25]
  sai3.TX_SYNC
  flexio1.FLEXIO[27]
  flexio1.FLEXIO[28]
  flexio1.FLEXIO[29]
sheet 3
- NOTE:
- I2C DEV TABLE
- PART
- DEVICE
- I2C ADDR
- PORT
- SPEED
- VOL
- DESCRIPTION
- U801
- PCAL6524HEAZ
- 0x22 (0b'01000[10]x)
- MX-I2C2
- 1MHz Fm+
- 3.3V
- IO EXP for IRQ/OUTPUT
- U301
- PTN5110NHQZ
- 0x52 (0b'10100[10]x)
- MX-I2C1
- 400KHz
- 3.3V
- USB C PD PHY
- U401
- PTN5110NHQZ
- 0x50 (0b'10100[00]x)
- MX-I2C1
- 400KHz
- 3.3V
- USB C PD PHY
- U402
- NX20P3483UK
- 0x71 (0b'11100[01]x)
- MX-I2C1
- 400KHz
- 3.3V
- USB Load Switch
- U1401
- LSM6DSOXTR
- 0x6A (0b'110101[0]x)
- MX-I2C1
- /I2C3
- I3C/I2C-400KHz
- 3.3V
- IMU (I3C support)
- U1709
- WM8962B
- 0x1A (0b'0011010x)
- MX-I2C1
- 526KHz
- 3.3V
- Audio CODEC
- U701
- PCA9451AHN
- 0x25 (0b'0100101x)
- MX-I2C2
- 1MHz Fm+
- 3.3V
- PMIC
- U1409
- PCA9655EMTTXG
- 0x21 (0b'0100001)
- FTDI-I2C
- 1MHz Fm+
- 3.3V
- RDPM IO EXP
- U915
- P3T1085UK
- 0x48 (0b'1001000x)
- MX-I2C1
- I3C/I2C-400KHz
- 3.3V
- Temp Sensor (I3C support)
- U1004
- PCF2131TF
- 0x53 (0b'1010011x)
- MX-I2C1
- 400KHz
- 3.3V
- Ext RTC
sheet 4
- SCREW HOLE
- GND TP
- GND TESTLOOP
- TOP Layer
